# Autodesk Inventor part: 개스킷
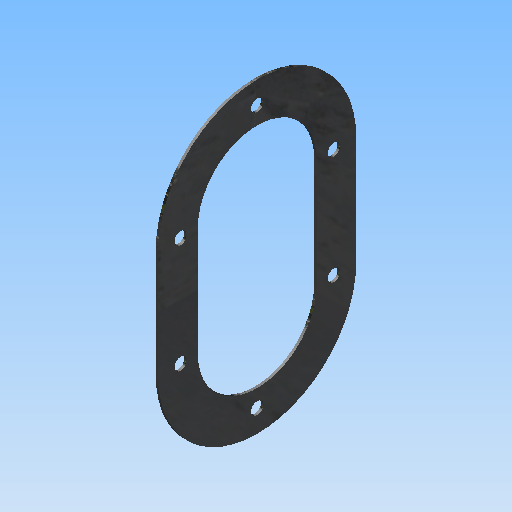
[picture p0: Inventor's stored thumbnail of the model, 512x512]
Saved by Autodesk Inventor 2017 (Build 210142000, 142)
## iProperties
Created: 2019-03
Part Number: 개스킷
Material: 고무
Document SubType Name: Modeling
Designer: mduedu
Density: 1 g/cm^3
Appearance: 고무 - 검은색 - 버전 1.1
Author: mduedu
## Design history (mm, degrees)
sketch "스케치1"
  geometry: L1 (-62, 40)-(62, 40); L2 (62, 40)-(62, -40); L3 (62, -40)-(-62, -40); L4 (-62, -40)-(-62, 40); L5 (-62, 40)-(62, -40); L6 (62, 40)-(-62, -40); 1 further point
  constraints: 12 end point, 2 midpoint, 2 parallel, 1 horizontal, 1 perpendicular
  dimensions: "d21" = 124 distance of L2.end L3.end; "d22" = 80 distance of L1.end L2.end
extrude "돌출1" new body sketch "스케치1" distance "d3" = 1; taper "d4" = 0 deg
fillet "모깎기2"
fillet "모깎기3"
sketch "스케치2" dims "d6" = 48
  geometry: L1 (-24, -22)-(24, -22); L2 (24, -22)-(24, 22); L3 (24, 22)-(-24, 22); L4 (-24, 22)-(-24, -22); L5 (-24, -22)-(24, 22); L6 (24, -22)-(-24, 22); 3 further points
  constraints: 12 end point, 4 midpoint, 2 horizontal alignment, 2 parallel, 1 horizontal, 1 perpendicular, 4 other
  dimensions: "d8" = 22 distance from line of L3 point (0, 0)
extrude "돌출2" cut sketch "스케치2" stored distance "d9" = 1; taper "d10" = 0 deg
sketch "스케치3"
  geometry: L1 (24, -22)-(24, 22) reference; L2 (-24, 22)-(-24, -22) reference; L3 (31, 22)-(31, -22); L4 (-31, -22)-(-31, 22); A1 r 24 centre (0, 22) between (24, 22) and (-24, 22) reference; A2 r 24 centre (0, -22) between (-24, -22) and (24, -22) reference; A3 r 31 centre (0, 22) between (31, 22) and (-31, 22); A4 r 31 centre (0, -22) between (-31, -22) and (31, -22); 7 further points
  constraints: 6 point on circle, 4 coincident, 4 end point, 2 centre point, 3 other
  dimensions: "d26" = 62 distance between parallel lines of L3 L4; "d28" = 7 distance between parallel lines of L4 L2 (derived); "d29" = 48 distance between parallel lines of L1 L2 (derived); "d30" = 31 radius of A3 (derived)
hole "구멍1" sketch "스케치3" at (0, 53), (31, 22), (31, -22), (0, -53), (-31, -22), (-31, 22) diameter "d14" = 5; stored, may be unused: countersink angle "d18" = 90 deg, drill point angle "d20" = 118 deg; dims "d15" = 6, "d16" = 4, "d17" = 2, "d19" = 8
node "솔리드1"
